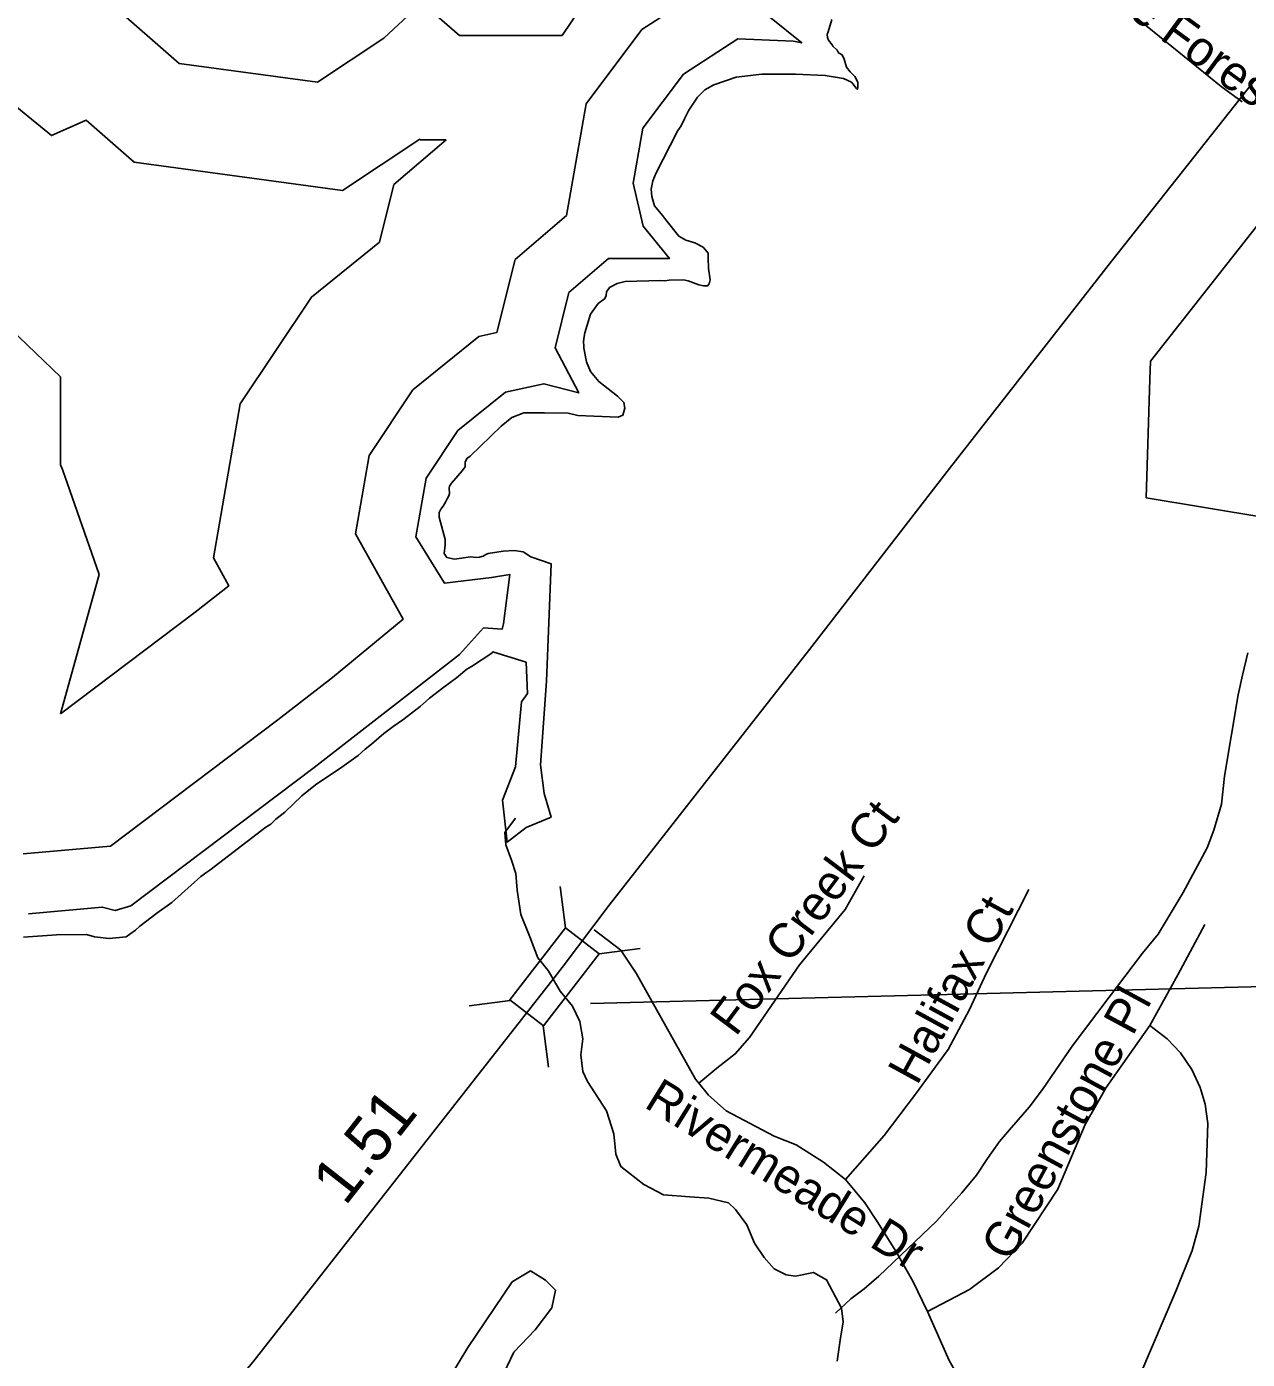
# Model space of a CAD drawing. Extents: x 1662474 to 1856135, y 779280 to 917889.
# Drawn here: x 1707278 to 1710599, y 822946 to 826573 of the extents above; entities that cross this region are included whole.
import ezdxf

# ---------------------------------------------------------------- set-up
doc = ezdxf.new("R2010")
doc.units = 0
for name, color, linetype in [('Exist Boundary Political City Limit New Hole', 7, 'Continuous'), ('Exist Hydrographic Creek Single Shore', 7, 'Continuous'), ('Exist Hydrographic Lake Shore', 7, 'Continuous'), ('Exist Hydrographic Misc Water Feature', 7, 'Continuous'), ('Exist Hydrographic Pond Under 1500 Sq Ft', 7, 'Continuous'), ('Exist Road Non-System Type 51', 7, 'Continuous'), ('Exist Road Non-System Type 51 Label', 7, 'Continuous'), ('Exist Road Primary NC Structure Standard Bridge CELL', 7, 'Continuous'), ('Exist Road Primary NC Structure Standard Bridge Number Label', 7, 'Continuous'), ('Exist Road Primary NC UnDivided 4 Lane Attributed', 7, 'Continuous'), ('Map Preparation Boundary City Limit Buffer Line', 7, 'Continuous'), ('Old_Level_44', 7, 'Continuous'), ('Prop Guardrail', 7, 'Continuous')]:
    doc.layers.add(name, color=color, linetype=linetype)

msp = doc.modelspace()

# ---------------------------------------------------------------- linework, layer by layer
at = {"layer": 'Exist Boundary Political City Limit New Hole'}
msp.add_lwpolyline([(1711049.8, 826569.4), (1710336.2, 825662.4), (1710334.6, 825613.5), (1710324.5, 825290.7), (1710647, 825237.2)], dxfattribs=at)
at = {"layer": 'Exist Hydrographic Creek Single Shore'}
msp.add_lwpolyline([(1708608.2, 824418.9), (1708579.1, 824379.8), (1708582.2, 824345.9), (1708596.9, 824303.9), (1708609.5, 824268.2), (1708612.6, 824222.9), (1708622.6, 824156.8), (1708646.8, 824095.3), (1708669.4, 824038.6), (1708697.2, 824004.5), (1708729.8, 823947.8), (1708763.4, 823907.4), (1708782.8, 823865.4), (1708791.1, 823818.1), (1708785.9, 823774.6), (1708791.1, 823729.4), (1708804, 823701.9), (1708855.8, 823622.4), (1708875.4, 823559.4), (1708881.5, 823504.2), (1708894.9, 823470.4), (1708957.5, 823421.6), (1709011.1, 823394), (1709082.5, 823388), (1709134.2, 823384.6), (1709187.5, 823371.7), (1709206.9, 823353.9), (1709237.9, 823311.9), (1709258.6, 823261.8), (1709284.6, 823222.9), (1709312.4, 823191.9), (1709344.4, 823175.6), (1709370.4, 823172.5), (1709419, 823182.2), (1709454.6, 823162.5), (1709495.1, 823085.1), (1709500.1, 823048.1), (1709491.6, 822997.7), (1709483.5, 822941.2)], dxfattribs=at)
at = {"layer": 'Exist Hydrographic Lake Shore'}
for points in [[(1709468.6, 826592.4), (1709458.9, 826558.8), (1709456, 826551.7), (1709457, 826543.6), (1709459.6, 826535.9), (1709469.4, 826523.6), (1709471.2, 826519.7), (1709483, 826508.9), (1709487.5, 826501.1), (1709496.9, 826496.1), (1709502.1, 826484.5), (1709508.8, 826462.7), (1709518.4, 826449.9), (1709531.5, 826437.2), (1709539.4, 826422.1), (1709539.4, 826407.1), (1709538.6, 826402.4), (1709535.8, 826404.7), (1709522.1, 826422.1), (1709500.6, 826431.2), (1709451, 826439.9), (1709369.9, 826443.6), (1709278.2, 826443.6), (1709208.2, 826435.2), (1709147.6, 826414.7), (1709123.1, 826400.8), (1709103.2, 826381.1), (1709080.1, 826345.1), (1709067.8, 826322.3), (1709059.4, 826303.1), (1709050.2, 826290), (1709029, 826249.3), (1708991.1, 826175.1), (1708981.8, 826152.8), (1708977.2, 826130.4), (1708978.9, 826110.8), (1708986.8, 826085.3), (1709000.4, 826068.5), (1709009.2, 826058.2), (1709017.1, 826047.2), (1709052.6, 826002.9), (1709071.8, 825991.3), (1709096.1, 825984.2), (1709118.8, 825972.7), (1709132.4, 825956.4), (1709132.4, 825943.8), (1709133.6, 825914.9), (1709137.6, 825883.8), (1709135, 825873.2), (1709130.8, 825867.2), (1709120, 825867.2), (1709106.6, 825869.8), (1709078.2, 825881.4), (1709064.9, 825883.8), (1709026.4, 825882.9), (1709014.2, 825881.4), (1709003, 825882.1), (1708906.9, 825879.5), (1708884.4, 825873.5), (1708864.1, 825863), (1708856, 825851.4), (1708854.6, 825840.2), (1708850.5, 825832), (1708832.9, 825819.2), (1708812.6, 825790.3), (1708796.6, 825739.4), (1708794.9, 825729.7), (1708793.5, 825716.2), (1708794.2, 825703.1), (1708794, 825697.4), (1708801.1, 825660.6), (1708812.6, 825634.1), (1708834.5, 825607.4), (1708885.6, 825566.7), (1708903, 825550.1), (1708905.9, 825534.1), (1708900.4, 825515.8), (1708887.2, 825509.7), (1708778, 825514.4), (1708751.2, 825520.5), (1708687, 825521.5), (1708631, 825521.5), (1708598, 825508.7), (1708569.4, 825485.6)], [(1708569.4, 825485.6), (1708484.6, 825403.7), (1708476.2, 825397.6), (1708471, 825387.1), (1708471, 825374.6), (1708463.1, 825364.3), (1708434.5, 825330.2), (1708429, 825322.1), (1708428.1, 825316.3), (1708429, 825302.6), (1708426.6, 825295.6), (1708422.9, 825289.8), (1708418.2, 825280.1), (1708411.1, 825267.4), (1708404.8, 825259.6), (1708400.9, 825250.1), (1708400.9, 825237.6), (1708417.1, 825177.4), (1708417.1, 825162.2), (1708414.2, 825139.1), (1708421.1, 825128.4), (1708442.6, 825123.1), (1708485.4, 825129.9), (1708501.9, 825127.8), (1708510, 825128.6), (1708520.2, 825131.8), (1708527.4, 825136), (1708534.2, 825139.1), (1708574.9, 825145.2), (1708604.2, 825147.5), (1708629, 825143.9), (1708650, 825130.2), (1708704.9, 825111.1), (1708692.6, 824791.2), (1708676, 824564.2), (1708686.4, 824485.8), (1708704.9, 824421.8), (1708636.8, 824393), (1708585.2, 824353.7), (1708572.9, 824467.2), (1708607.9, 824558), (1708624.5, 824735.5), (1708641, 824758.2), (1708636.8, 824842.8), (1708546.2, 824870.9), (1708543.6, 824868), (1708488.2, 824831), (1708476.2, 824823.9), (1708447.9, 824800.8), (1708413, 824775.1), (1708373.9, 824744.9), (1708348.4, 824722.1), (1708301.4, 824686.1), (1708275.6, 824668.5), (1708250, 824648.8), (1708216.1, 824620), (1708199, 824606.3), (1708179.9, 824589.5), (1708135.5, 824557.2), (1708064.4, 824509.8), (1708026.6, 824479.3), (1707980.9, 824435.2), (1707956.2, 824415.5), (1707942.1, 824402.6), (1707928.8, 824393.8), (1707776.5, 824277.2), (1707767.9, 824271.7), (1707752.1, 824260.1), (1707672.8, 824189.2), (1707632.4, 824160.1), (1707586.5, 824124.4), (1707573.9, 824113.4), (1707558.4, 824103.4), (1707548.6, 824096.1), (1707502.8, 824091.6), (1707462.6, 824096.1), (1707441, 824102.1), (1707358.9, 824100.8), (1707269.9, 824095.1)]]:
    msp.add_lwpolyline(points, dxfattribs=at)
at = {"layer": 'Exist Hydrographic Misc Water Feature'}
msp.add_lwpolyline([(1710600.9, 824868.5), (1710586.6, 824808.1), (1710574.2, 824754.2), (1710537.1, 824532.6), (1710528.8, 824456.4), (1710508.3, 824386.3), (1710490, 824338.2), (1710425.2, 824216.4), (1710356.7, 824102.9), (1710314.3, 824051.3), (1710265.9, 823987.4), (1710223.6, 823931.7), (1710122.8, 823798.3), (1710041.9, 823680.2), (1710005.7, 823632.5), (1709957.4, 823576.9), (1709925.3, 823538.9), (1709892.9, 823492.8), (1709862.7, 823446.7), (1709822.3, 823399), (1709754.1, 823321.7), (1709596.9, 823172.3), (1709556.6, 823137.8), (1709520.4, 823110.6), (1709478.8, 823071.2)], dxfattribs=at)
at = {"layer": 'Exist Hydrographic Pond Under 1500 Sq Ft'}
msp.add_lwpolyline([(1708689.4, 823161.5), (1708649.2, 823186.6), (1708598.9, 823156.4), (1708478.3, 822978.1), (1708412.9, 822870.1), (1708400.3, 822832.4), (1708435.5, 822824.8), (1708483.3, 822847.4), (1708528.5, 822852.5), (1708566.2, 822887.6), (1708603.9, 822965.5), (1708661.7, 823025.8), (1708707, 823086.1), (1708717, 823133.8), (1708689.4, 823161.5)], dxfattribs=at)
at = {"layer": 'Exist Road Non-System Type 51'}
for points in [[(1710585.4, 826367.7), (1710528.6, 826410.2), (1710058, 826791.4), (1709988, 826845.1), (1709934.1, 826877.1), (1709883, 826898.4), (1709786.4, 826915.7), (1709739.9, 826918.4), (1709618.4, 826913.6), (1709531, 826900.8), (1709507.1, 826895), (1709443.1, 826858.5), (1709410.9, 826823.4), (1709378.5, 826774)], [(1709106.9, 823697.4), (1709156, 823738.6), (1709206.1, 823776.9), (1709244.6, 823821.9), (1709380.9, 824019.9), (1709505, 824169.9), (1709557, 824261.9)], [(1709506.1, 823435.2), (1709611.4, 823554.9), (1709696.6, 823667.8), (1709785.1, 823789.5), (1709843.6, 823897.7), (1709889.9, 823997.7), (1710005, 824224.9)], [(1709106.9, 823697.4), (1709097.9, 823708.4), (1708936.2, 823996.6), (1708894.6, 824059.6), (1708822.1, 824115)], [(1710333.9, 823854.6), (1710410, 823991.9), (1710484, 824129.4)], [(1709728.9, 823075.6), (1709843.6, 823136.2), (1709922.6, 823194.8), (1709987.1, 823262.2), (1710084.2, 823408.7), (1710158, 823584.9), (1710215.2, 823685.4), (1710333.9, 823854.6)], [(1710187.1, 822499.2), (1710210.9, 822555.2), (1710228.9, 822618.9), (1710249.4, 822754.4), (1710274.9, 822827.6), (1710405.2, 823131.8), (1710448.9, 823242), (1710467.2, 823307.9), (1710487.6, 823454.6), (1710492.1, 823587.4), (1710484.6, 823640.4), (1710470.9, 823686.1), (1710448.1, 823734.9), (1710417.9, 823779.6), (1710380.9, 823818.4), (1710333.9, 823854.6)], [(1709506.1, 823435.2), (1709445.8, 823482.2), (1709371.6, 823529.9), (1709312.1, 823552.8), (1709181.1, 823622.6), (1709133.4, 823664.9), (1709106.9, 823697.4)], [(1709728.9, 823075.6), (1709689.6, 823158.4), (1709643.1, 823239.9), (1709592.4, 823320.8), (1709559.1, 823371.7), (1709506.1, 823435.2)], [(1710187.1, 822499.2), (1710095.4, 822565.2), (1709975.4, 822679), (1709875.4, 822806.4), (1709824.1, 822879.6), (1709788.2, 822942.6), (1709728.9, 823075.6)]]:
    msp.add_lwpolyline(points, dxfattribs=at)
at = {"layer": 'Exist Road Primary NC Structure Standard Bridge CELL'}
for p, q in [((1708729.3, 824232.6), (1708743.8, 824120.3)), ((1708947.7, 824064.1), (1708835.4, 824049.6)), ((1708594, 823922.8), (1708481.8, 823908.3)), ((1708683.6, 823853.7), (1708698.1, 823741.4))]:
    msp.add_line(p, q, dxfattribs=at)
msp.add_lwpolyline([(1708835.4, 824049.6), (1708684, 823853.3), (1708592.4, 823924.1), (1708743.8, 824120.3)], close=True, dxfattribs=at)
at = {"layer": 'Exist Road Primary NC Structure Standard Bridge Number Label'}
msp.add_line((1708812.4, 823914.2), (1710918.3, 823967.1), dxfattribs=at)
at = {"layer": 'Exist Road Primary NC UnDivided 4 Lane Attributed'}
for points in [[(1708713.1, 823984.5), (1708734.8, 824012.4), (1708863.3, 824181.6), (1709407.9, 824877.3), (1709789.2, 825370.3), (1710230.9, 825935.7), (1710645.8, 826460.4), (1710999, 826917.6), (1711346.5, 827434.4), (1711398.8, 827522)], [(1706788.9, 821401.4), (1706839.3, 821494.6), (1706962.1, 821724.4), (1707037.7, 821859.8), (1707122.7, 821982.6), (1707180.7, 822057), (1707267, 822170), (1707379.5, 822314.1), (1707719.8, 822733.4), (1707893.1, 822938), (1708713.1, 823984.5)]]:
    msp.add_lwpolyline(points, dxfattribs=at)
at = {"layer": 'Map Preparation Boundary City Limit Buffer Line'}
msp.add_lwpolyline([(1711049.8, 826569.4), (1710336.2, 825662.4), (1710334.6, 825613.5), (1710324.5, 825290.7), (1710647, 825237.2)], dxfattribs=at)
at = {"layer": 'Old_Level_44'}
for points in [[(1708420, 826265.1), (1708349.1, 826265.1), (1708347.7, 826266.3), (1708137.7, 826126.4), (1707570.3, 826203.7), (1707439.7, 826317.9), (1707345.7, 826276.2), (1707041.9, 826524.6), (1706975.9, 826554.3), (1706854.2, 826573), (1706366, 826782.1), (1706321.1, 827321.6), (1706456.4, 827727.4), (1706625.8, 827883.7), (1706744, 828083.1), (1706798.2, 828171.6), (1706646.7, 828238.8), (1706416.7, 828453.3)], [(1709484.9, 827557.2), (1709247.8, 827438.7), (1709081.2, 827477.9), (1709081.2, 827434), (1709109.6, 827416.9), (1709157.6, 827105.6), (1709050.4, 826873.5), (1708903.7, 826726.9), (1708817.4, 826672), (1708734.9, 826548.3), (1708455.5, 826548.3), (1708353.7, 826637.3), (1708249.7, 826541.3), (1708069.8, 826421.5), (1707692.7, 826472.9), (1707505, 826637), (1707500.2, 826654.7), (1707390, 826605.8), (1707192.2, 826767.5)], [(1708747.4, 826058.9), (1708800.3, 826362.8), (1708951.7, 826564.6), (1709055.9, 826632.5), (1709111, 826889.4), (1709260.7, 827068.9), (1709443.6, 827148.4), (1709408.2, 827301.8), (1709484.9, 827557.2)], [(1707283.4, 824158.6), (1707483.8, 824176.6), (1707518.9, 824167.8), (1707561.9, 824180.1), (1708060.7, 824556.5), (1708455.7, 824864.1), (1708520.7, 824936.3), (1708571.5, 824932.7), (1708575.7, 824947.3), (1708592.9, 825081.4), (1708542.7, 825073.9), (1708415.3, 825058), (1708337.2, 825184.7), (1708364.9, 825343.7), (1708451.4, 825473.3), (1708581.2, 825578.4), (1708685.7, 825600.8), (1708780.4, 825575.9), (1708715.7, 825698.7), (1708753.3, 825848.9), (1708861.6, 825941.7), (1708987.6, 825941.7), (1709026.8, 825941.7), (1708956, 826030.1), (1708928.5, 826146.8), (1708954.5, 826296.1), (1709065.1, 826443.4), (1709212.9, 826539.8), (1709364.4, 826533.5), (1709387.1, 826529.1), (1709299.5, 826599.1)], [(1705802, 826302.9), (1705990.5, 826130.7), (1706064.5, 826204.7), (1706334, 826227.1), (1706604.9, 826227.1), (1706798.3, 826047.6), (1706817.5, 826036.8), (1706868, 826016), (1707031.1, 825944.7), (1707370, 825620.1), (1707370, 825379.8), (1707375.7, 825367.6), (1707475.1, 825081.9), (1707369.8, 824702.7)], [(1707369.8, 824702.7), (1707736.4, 824979.5), (1707828.4, 825051.1), (1707786.2, 825126.7), (1707859.2, 825545.9), (1708053.1, 825836.6), (1708238.4, 825986.5), (1708277.5, 826143), (1708420, 826265.1)], [(1707268.8, 824321.3), (1707506, 824342.6), (1707961.3, 824686.1), (1708109.9, 824801.9), (1708302.4, 824959.8), (1708172.8, 825192.3), (1708209.9, 825405.7), (1708329.3, 825584.7), (1708508.8, 825729.9), (1708557.8, 825740.4), (1708607.5, 825939), (1708747.4, 826058.9)]]:
    msp.add_lwpolyline(points, dxfattribs=at)

# ---------------------------------------------------------------- texts
at = {"layer": 'Exist Road Non-System Type 51 Label'}
for s, rotation, p in [('Lake Forest Dr', 323.7786, (1710107.3, 826724.3)), ('Fox Creek Ct', 53.1926, (1709207.4, 823821.8)), ('Halifax Ct', 61.3179, (1709700.8, 823688.9)), ('Greenstone Pl', 61.5637, (1709954.6, 823208.6)), ('Rivermeade Dr', 328.284, (1708955, 823633.9))]:
    msp.add_text(s, height=95, rotation=rotation, dxfattribs=at).set_placement(p)
at = {"layer": 'Prop Guardrail'}
msp.add_text('1.51', height=125, rotation=51.9185, dxfattribs=at).set_placement((1708145, 823360.8))

doc.saveas('drawing.dxf')
